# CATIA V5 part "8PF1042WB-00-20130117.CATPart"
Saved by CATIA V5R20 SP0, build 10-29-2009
Part number: 8PF1042WB-00-20130117
Revision: ANY
Definition: UNKNOWN
Nomenclature: 8PF1042WB-00-20130117
Source: Unknown
Bounding box of the stored display mesh (mm): x 1681.921 to 1881.921, y 1457.713 to 1464.638, z 0 to 10
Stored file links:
  C:\Users\Utente\Desktop\IO LAVORO\3D X SITO CF\CUMSA\3D files PF\PF 1042WB\8PF1042WB-00-20130117.CATPart
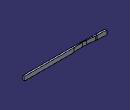
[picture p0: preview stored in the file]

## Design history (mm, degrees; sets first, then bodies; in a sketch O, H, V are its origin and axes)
Body1 "Cortar-Extruir1" (main body)
  Solid1: solid without history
